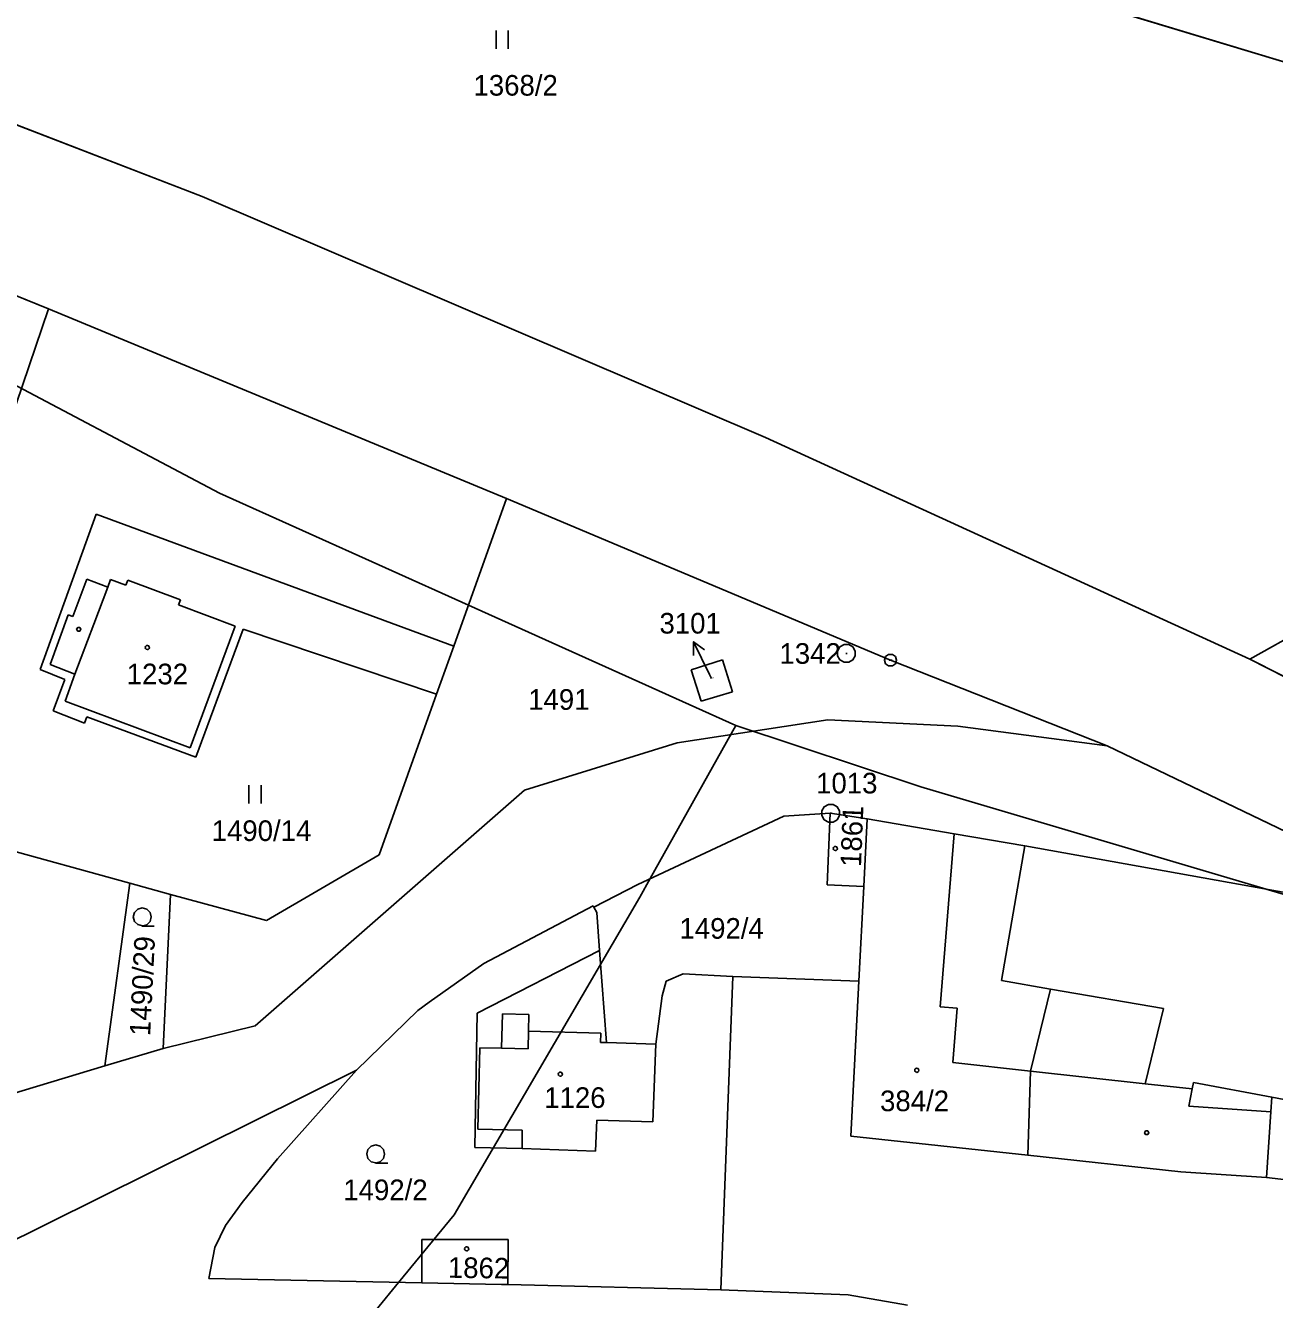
# Model space of a CAD drawing. Extents: x -779618 to -776429, y -1144546 to -1143350.
# Drawn here: x -777476.8 to -777373.9, y -1143853.5 to -1143748.5 of the extents above; entities that cross this region are included whole.
import ezdxf

# ---------------------------------------------------------------- set-up
doc = ezdxf.new("R2010")
doc.units = 0
for name, color, linetype in [('1', 7, 'Continuous'), ('11', 7, 'Continuous'), ('12', 7, 'Continuous'), ('2', 7, 'Continuous'), ('3', 7, 'Continuous'), ('4', 7, 'Continuous'), ('5', 7, 'Continuous'), ('7', 7, 'Continuous'), ('8', 7, 'Continuous')]:
    doc.layers.add(name, color=color, linetype=linetype)

msp = doc.modelspace()

# ---------------------------------------------------------------- linework, layer by layer
at = {"layer": '1'}
for p, q in [((-777547.63, -1143698.79), (-777364.95, -1143754.01)), ((-777556.08, -1143726.43), (-777462.27, -1143762.62)), ((-777415.86, -1143782.49), (-777462.27, -1143762.62)), ((-777494.83, -1143763.84), (-777474.95, -1143771.88)), ((-777487.19, -1143807.86), (-777474.95, -1143771.88)), ((-777437.2, -1143787.51), (-777474.95, -1143771.88)), ((-777375.94, -1143800.75), (-777415.86, -1143782.49)), ((-777375.94, -1143800.75), (-777349.24, -1143785.82)), ((-777441.55, -1143799.67), (-777437.2, -1143787.51)), ((-777405.54, -1143800.83), (-777437.2, -1143787.51)), ((-777471.01, -1143788.8), (-777475.63, -1143801.6)), ((-777441.55, -1143799.67), (-777471.01, -1143788.8)), ((-777462.81, -1143808.82), (-777458.9, -1143798.28)), ((-777458.9, -1143798.28), (-777442.96, -1143803.61)), ((-777442.96, -1143803.61), (-777441.55, -1143799.67)), ((-777421.98, -1143801.63), (-777419.39, -1143800.8)), ((-777419.39, -1143800.8), (-777418.56, -1143803.42)), ((-777387.68, -1143807.89), (-777405.54, -1143800.83)), ((-777334.23, -1143821.79), (-777375.94, -1143800.75)), ((-777475.63, -1143801.6), (-777473.61, -1143802.41)), ((-777421.16, -1143804.21), (-777421.98, -1143801.63)), ((-777473.61, -1143802.41), (-777474.56, -1143805)), ((-777447.69, -1143816.85), (-777442.96, -1143803.61)), ((-777418.56, -1143803.42), (-777421.16, -1143804.21)), ((-777474.56, -1143805), (-777471.98, -1143806.02)), ((-777471.98, -1143806.02), (-777471.78, -1143805.5)), ((-777471.78, -1143805.5), (-777462.81, -1143808.82)), ((-777423.12, -1143807.62), (-777410.71, -1143805.75)), ((-777410.71, -1143805.75), (-777400, -1143806.27)), ((-777400, -1143806.27), (-777387.68, -1143807.89)), ((-777435.72, -1143811.54), (-777423.12, -1143807.62)), ((-777356.13, -1143823.03), (-777387.68, -1143807.89)), ((-777457.92, -1143830.94), (-777435.72, -1143811.54)), ((-777489.08, -1143813.43), (-777468.25, -1143819.2)), ((-777410.51, -1143813.42), (-777414.33, -1143813.66)), ((-777410.76, -1143819.32), (-777410.51, -1143813.42)), ((-777407.46, -1143813.89), (-777410.51, -1143813.42)), ((-777414.33, -1143813.66), (-777426.36, -1143819.29)), ((-777407.75, -1143819.47), (-777407.46, -1143813.89)), ((-777400.29, -1143815.13), (-777407.46, -1143813.89)), ((-777394.47, -1143816.13), (-777400.29, -1143815.13)), ((-777394.47, -1143816.13), (-777396.39, -1143827.22)), ((-777369.47, -1143820.6), (-777394.47, -1143816.13)), ((-777456.98, -1143822.28), (-777447.69, -1143816.85)), ((-777468.25, -1143819.2), (-777470.29, -1143834.25)), ((-777468.25, -1143819.2), (-777464.88, -1143820.14)), ((-777430, -1143821.16), (-777426.36, -1143819.29)), ((-777407.75, -1143819.47), (-777410.76, -1143819.32)), ((-777408.15, -1143827.26), (-777407.75, -1143819.47)), ((-777464.88, -1143820.14), (-777465.49, -1143832.81)), ((-777464.88, -1143820.14), (-777456.98, -1143822.28)), ((-777430.05, -1143821.07), (-777439.06, -1143825.81)), ((-777430, -1143821.16), (-777430.05, -1143821.07)), ((-777430, -1143821.16), (-777429.76, -1143821.62)), ((-777429.52, -1143824.74), (-777429.76, -1143821.62)), ((-777429.52, -1143824.74), (-777439.62, -1143829.91)), ((-777429.52, -1143824.74), (-777428.95, -1143832.33)), ((-777439.06, -1143825.81), (-777443.57, -1143828.99)), ((-777422.63, -1143826.67), (-777424.04, -1143827.28)), ((-777418.55, -1143826.88), (-777422.63, -1143826.67)), ((-777419.52, -1143852.7), (-777418.55, -1143826.88)), ((-777408.15, -1143827.26), (-777418.55, -1143826.88)), ((-777396.39, -1143827.22), (-777392.36, -1143827.92)), ((-777424.04, -1143827.28), (-777424.38, -1143828.48)), ((-777408.15, -1143827.26), (-777408.81, -1143840.04)), ((-777392.36, -1143827.92), (-777394, -1143834.68)), ((-777443.57, -1143828.99), (-777444.5, -1143829.67)), ((-777424.9, -1143832.45), (-777424.38, -1143828.48)), ((-777444.5, -1143829.67), (-777449.55, -1143834.59)), ((-777439.81, -1143840.98), (-777439.62, -1143829.91)), ((-777465.49, -1143832.81), (-777457.92, -1143830.94)), ((-777428.95, -1143832.33), (-777424.9, -1143832.45)), ((-777424.9, -1143832.45), (-777425.13, -1143838.85)), ((-777465.49, -1143832.81), (-777470.29, -1143834.25)), ((-777470.29, -1143834.25), (-777506.15, -1143845.05)), ((-777449.55, -1143834.59), (-777486.78, -1143853.07)), ((-777449.55, -1143834.59), (-777456.06, -1143841.9)), ((-777394, -1143834.68), (-777394.22, -1143841.61)), ((-777374.13, -1143836.83), (-777374.21, -1143838.03)), ((-777347.87, -1143841.8), (-777374.13, -1143836.83)), ((-777429.76, -1143838.71), (-777429.86, -1143841.27)), ((-777425.13, -1143838.85), (-777429.76, -1143838.71)), ((-777374.21, -1143838.03), (-777374.57, -1143843.43)), ((-777394.22, -1143841.61), (-777408.81, -1143840.04)), ((-777456.06, -1143841.9), (-777458.98, -1143845.51)), ((-777435.91, -1143841.04), (-777439.81, -1143840.98)), ((-777429.86, -1143841.27), (-777435.91, -1143841.04)), ((-777381.61, -1143842.97), (-777394.22, -1143841.61)), ((-777374.57, -1143843.43), (-777381.61, -1143842.97)), ((-777374.57, -1143843.43), (-777344.36, -1143847.04)), ((-777458.98, -1143845.51), (-777460.37, -1143847.4)), ((-777460.37, -1143847.4), (-777461.25, -1143849.21)), ((-777461.25, -1143849.21), (-777461.74, -1143851.77)), ((-777444.18, -1143852.13), (-777444.17, -1143848.54)), ((-777444.17, -1143848.54), (-777437.07, -1143848.56)), ((-777437.07, -1143848.56), (-777437.09, -1143852.27)), ((-777461.74, -1143851.77), (-777444.18, -1143852.13)), ((-777444.18, -1143852.13), (-777437.61, -1143852.26)), ((-777437.61, -1143852.26), (-777437.09, -1143852.27)), ((-777437.09, -1143852.27), (-777419.52, -1143852.7)), ((-777409.04, -1143853.1), (-777419.52, -1143852.7)), ((-777404.16, -1143853.96), (-777409.04, -1143853.1))]:
    msp.add_line(p, q, dxfattribs=at)
at = {"layer": '11'}
for points in [[(-777547.63, -1143698.79), (-777364.95, -1143754.01), (-777362.08, -1143759.74), (-777358.14, -1143760.61), (-777354.56, -1143760.13), (-777348.72, -1143768.82), (-777340.59, -1143770.61), (-777339.43, -1143766.44), (-777335.02, -1143764.48), (-777321.99, -1143767.59), (-777306.65, -1143771.6), (-777305.36, -1143768.26), (-777286.39, -1143773.98), (-777252.03, -1143784.34), (-777238.03, -1143787.25), (-777223.03, -1143791.52), (-777208.67, -1143795.71)], [(-777215.44, -1143846.33), (-777291.06, -1143838.91), (-777294.79, -1143837.91), (-777307.07, -1143834.06), (-777326.59, -1143824.61), (-777334.23, -1143821.79), (-777375.94, -1143800.75), (-777415.86, -1143782.49), (-777462.27, -1143762.62), (-777554.92, -1143726.88)], [(-777521.49, -1143753.86), (-777516.57, -1143757.49), (-777516.32, -1143757.62), (-777506.06, -1143763.09), (-777499.08, -1143767.2), (-777481.34, -1143776.24), (-777460.86, -1143787.05), (-777440.34, -1143796.28), (-777418.3, -1143806.19)], [(-777521.49, -1143753.86), (-777515.73, -1143755.37), (-777494.83, -1143763.84), (-777474.95, -1143771.88), (-777437.2, -1143787.51), (-777405.54, -1143800.83), (-777387.68, -1143807.89), (-777356.13, -1143823.03), (-777352.24, -1143824.36), (-777344.73, -1143827.04), (-777336.84, -1143829.8), (-777324.83, -1143836.1), (-777303.85, -1143844.86), (-777292.27, -1143847.75), (-777289.53, -1143848.43), (-777281.88, -1143848.9), (-777167.58, -1143858.82), (-777035.36, -1143870.54), (-777014.02, -1143874.66), (-776998.39, -1143882.22), (-776992.99, -1143881.07), (-776972.79, -1143876.78), (-776970.83, -1143876.37), (-776959.34, -1143880.62)], [(-777497.86, -1143963.05), (-777497.46, -1143948.45), (-777496.32, -1143934.15), (-777492.21, -1143927.38), (-777485.12, -1143915.71), (-777483.6, -1143913.21), (-777468.38, -1143879.27), (-777447.94, -1143854.35), (-777446.1, -1143852.09), (-777441.52, -1143846.51), (-777426.21, -1143820.36), (-777425.35, -1143818.82), (-777418.3, -1143806.19)], [(-777418.3, -1143806.19), (-777403.06, -1143811.25), (-777374.59, -1143819.68), (-777369.17, -1143821.29), (-777341.76, -1143831.4), (-777336.43, -1143834.11), (-777325.63, -1143839.6), (-777311.72, -1143846.67), (-777306.4, -1143849.25), (-777294.09, -1143855.23), (-777285.59, -1143859.36), (-777258.07, -1143878.57), (-777228.36, -1143900.38)]]:
    msp.add_lwpolyline(points, dxfattribs=at)
at = {"layer": '12'}
for p, q in [((-777469.84, -1143794.17), (-777470.07, -1143794.8)), ((-777468.56, -1143794.65), (-777469.84, -1143794.17)), ((-777468.4, -1143794.23), (-777468.56, -1143794.65)), ((-777464.08, -1143795.85), (-777468.4, -1143794.23)), ((-777471.21, -1143797.86), (-777470.07, -1143794.8)), ((-777464.24, -1143796.27), (-777464.08, -1143795.85)), ((-777459.56, -1143798.03), (-777464.24, -1143796.27)), ((-777472.78, -1143801.97), (-777471.21, -1143797.86)), ((-777459.56, -1143798.03), (-777463.27, -1143808.03)), ((-777473.56, -1143804.21), (-777472.78, -1143801.97)), ((-777463.27, -1143808.03), (-777473.56, -1143804.21)), ((-777410.76, -1143819.32), (-777410.51, -1143813.42)), ((-777407.46, -1143813.89), (-777410.51, -1143813.42)), ((-777407.75, -1143819.47), (-777407.46, -1143813.89)), ((-777407.75, -1143819.47), (-777407.46, -1143813.89)), ((-777400.29, -1143815.13), (-777407.46, -1143813.89)), ((-777401.46, -1143829.38), (-777400.29, -1143815.13)), ((-777394.47, -1143816.13), (-777396.39, -1143827.22)), ((-777369.47, -1143820.6), (-777394.47, -1143816.13)), ((-777407.75, -1143819.47), (-777410.76, -1143819.32)), ((-777408.15, -1143827.26), (-777407.75, -1143819.47)), ((-777396.39, -1143827.22), (-777392.36, -1143827.92)), ((-777408.15, -1143827.26), (-777408.81, -1143840.04)), ((-777392.36, -1143827.92), (-777383.05, -1143829.53)), ((-777400.06, -1143829.5), (-777401.46, -1143829.38)), ((-777400.42, -1143833.97), (-777400.06, -1143829.5)), ((-777383.05, -1143829.53), (-777384.55, -1143835.72)), ((-777435.42, -1143832.85), (-777435.38, -1143831.38)), ((-777429.42, -1143831.56), (-777435.38, -1143831.38)), ((-777429.45, -1143832.31), (-777429.42, -1143831.56)), ((-777428.95, -1143832.33), (-777429.45, -1143832.31)), ((-777428.95, -1143832.33), (-777424.9, -1143832.45)), ((-777424.9, -1143832.45), (-777425.13, -1143838.85)), ((-777439.39, -1143832.75), (-777439.56, -1143839.47)), ((-777437.6, -1143832.8), (-777439.39, -1143832.75)), ((-777437.6, -1143832.8), (-777435.42, -1143832.85)), ((-777394, -1143834.68), (-777400.42, -1143833.97)), ((-777394, -1143834.68), (-777394.22, -1143841.61)), ((-777380.58, -1143835.61), (-777380.68, -1143836.15)), ((-777374.13, -1143836.83), (-777380.58, -1143835.61)), ((-777384.55, -1143835.72), (-777380.68, -1143836.15)), ((-777347.87, -1143841.8), (-777374.13, -1143836.83)), ((-777429.76, -1143838.71), (-777429.86, -1143841.27)), ((-777425.13, -1143838.85), (-777429.76, -1143838.71)), ((-777439.56, -1143839.47), (-777435.91, -1143839.53)), ((-777435.91, -1143839.53), (-777435.91, -1143841.04)), ((-777394.22, -1143841.61), (-777408.81, -1143840.04)), ((-777429.86, -1143841.27), (-777435.91, -1143841.04)), ((-777444.18, -1143852.13), (-777444.17, -1143848.54)), ((-777444.17, -1143848.54), (-777437.07, -1143848.56)), ((-777437.07, -1143848.56), (-777437.09, -1143852.27)), ((-777444.18, -1143852.13), (-777437.61, -1143852.26)), ((-777437.61, -1143852.26), (-777437.09, -1143852.27))]:
    msp.add_line(p, q, dxfattribs=at)
at = {"layer": '3'}
for p, q in [((-777438.05, -1143748.95), (-777438.05, -1143750.45)), ((-777437.05, -1143750.45), (-777437.05, -1143748.95)), ((-777458.43, -1143811.12), (-777458.43, -1143812.62)), ((-777457.43, -1143812.62), (-777457.43, -1143811.12))]:
    msp.add_line(p, q, dxfattribs=at)
for points in [[(-777467.21, -1143822.71), (-777467.59, -1143822.61), (-777467.86, -1143822.34), (-777467.96, -1143821.97), (-777467.86, -1143821.6), (-777467.59, -1143821.33), (-777467.22, -1143821.23), (-777466.85, -1143821.33), (-777466.58, -1143821.6), (-777466.48, -1143821.98), (-777466.58, -1143822.36), (-777466.85, -1143822.63), (-777467.23, -1143822.73), (-777466.23, -1143822.73)], [(-777447.97, -1143842.24), (-777448.35, -1143842.14), (-777448.62, -1143841.87), (-777448.72, -1143841.5), (-777448.62, -1143841.13), (-777448.35, -1143840.86), (-777447.98, -1143840.76), (-777447.61, -1143840.86), (-777447.34, -1143841.13), (-777447.24, -1143841.51), (-777447.34, -1143841.89), (-777447.61, -1143842.16), (-777447.99, -1143842.26), (-777446.99, -1143842.26)]]:
    msp.add_lwpolyline(points, dxfattribs=at)
at = {"layer": '4'}
for p, q in [((-777472.93, -1143797.23), (-777471.79, -1143794.16)), ((-777471.79, -1143794.16), (-777470.07, -1143794.8)), ((-777469.84, -1143794.17), (-777470.07, -1143794.8)), ((-777468.56, -1143794.65), (-777469.84, -1143794.17)), ((-777468.4, -1143794.23), (-777468.56, -1143794.65)), ((-777464.08, -1143795.85), (-777468.4, -1143794.23)), ((-777471.21, -1143797.86), (-777470.07, -1143794.8)), ((-777464.24, -1143796.27), (-777464.08, -1143795.85)), ((-777459.56, -1143798.03), (-777464.24, -1143796.27)), ((-777474.81, -1143801.17), (-777473.33, -1143797.08)), ((-777473.33, -1143797.08), (-777472.93, -1143797.23)), ((-777472.78, -1143801.97), (-777471.21, -1143797.86)), ((-777459.56, -1143798.03), (-777463.27, -1143808.03)), ((-777472.78, -1143801.97), (-777474.81, -1143801.17)), ((-777473.56, -1143804.21), (-777472.78, -1143801.97)), ((-777463.27, -1143808.03), (-777473.56, -1143804.21)), ((-777401.46, -1143829.38), (-777400.29, -1143815.13)), ((-777392.36, -1143827.92), (-777383.05, -1143829.53)), ((-777437.6, -1143832.8), (-777437.52, -1143829.97)), ((-777435.35, -1143830.02), (-777437.52, -1143829.97)), ((-777435.38, -1143831.38), (-777435.35, -1143830.02)), ((-777400.06, -1143829.5), (-777401.46, -1143829.38)), ((-777400.42, -1143833.97), (-777400.06, -1143829.5)), ((-777383.05, -1143829.53), (-777384.55, -1143835.72)), ((-777435.42, -1143832.85), (-777435.38, -1143831.38)), ((-777429.42, -1143831.56), (-777435.38, -1143831.38)), ((-777429.45, -1143832.31), (-777429.42, -1143831.56)), ((-777428.95, -1143832.33), (-777429.45, -1143832.31)), ((-777439.39, -1143832.75), (-777439.56, -1143839.47)), ((-777437.6, -1143832.8), (-777439.39, -1143832.75)), ((-777437.6, -1143832.8), (-777435.42, -1143832.85)), ((-777394, -1143834.68), (-777400.42, -1143833.97)), ((-777384.55, -1143835.72), (-777394, -1143834.68)), ((-777380.58, -1143835.61), (-777380.68, -1143836.15)), ((-777374.13, -1143836.83), (-777380.58, -1143835.61)), ((-777384.55, -1143835.72), (-777380.68, -1143836.15)), ((-777380.68, -1143836.15), (-777380.95, -1143837.57)), ((-777380.95, -1143837.57), (-777374.21, -1143838.03)), ((-777439.56, -1143839.47), (-777435.91, -1143839.53)), ((-777435.91, -1143839.53), (-777435.91, -1143841.04))]:
    msp.add_line(p, q, dxfattribs=at)
at = {"layer": '5'}
for points in [[(-777472.36, -1143798.13), (-777472.27, -1143798.28), (-777472.36, -1143798.43), (-777472.54, -1143798.43), (-777472.63, -1143798.28), (-777472.54, -1143798.13)], [(-777466.8, -1143799.61), (-777466.7, -1143799.63), (-777466.65, -1143799.72), (-777466.63, -1143799.78), (-777466.65, -1143799.87), (-777466.73, -1143799.94), (-777466.8, -1143799.95), (-777466.89, -1143799.92), (-777466.95, -1143799.86), (-777466.97, -1143799.78), (-777466.95, -1143799.69), (-777466.87, -1143799.62)], [(-777410.09, -1143816.17), (-777409.99, -1143816.19), (-777409.94, -1143816.28), (-777409.92, -1143816.34), (-777409.94, -1143816.43), (-777410.02, -1143816.5), (-777410.09, -1143816.51), (-777410.18, -1143816.48), (-777410.24, -1143816.42), (-777410.26, -1143816.34), (-777410.24, -1143816.25), (-777410.16, -1143816.18)], [(-777403.38, -1143834.44), (-777403.28, -1143834.46), (-777403.23, -1143834.55), (-777403.21, -1143834.61), (-777403.23, -1143834.7), (-777403.31, -1143834.77), (-777403.38, -1143834.78), (-777403.47, -1143834.75), (-777403.53, -1143834.69), (-777403.55, -1143834.61), (-777403.53, -1143834.52), (-777403.45, -1143834.45)], [(-777432.76, -1143834.76), (-777432.66, -1143834.78), (-777432.61, -1143834.87), (-777432.59, -1143834.93), (-777432.61, -1143835.02), (-777432.69, -1143835.09), (-777432.76, -1143835.1), (-777432.85, -1143835.07), (-777432.91, -1143835.01), (-777432.93, -1143834.93), (-777432.91, -1143834.84), (-777432.83, -1143834.77)], [(-777384.34, -1143839.6), (-777384.25, -1143839.75), (-777384.34, -1143839.9), (-777384.52, -1143839.9), (-777384.61, -1143839.75), (-777384.52, -1143839.6)], [(-777440.48, -1143849.15), (-777440.38, -1143849.17), (-777440.33, -1143849.26), (-777440.31, -1143849.32), (-777440.33, -1143849.41), (-777440.41, -1143849.48), (-777440.48, -1143849.49), (-777440.57, -1143849.46), (-777440.63, -1143849.4), (-777440.65, -1143849.32), (-777440.63, -1143849.23), (-777440.55, -1143849.16)]]:
    msp.add_lwpolyline(points, close=True, dxfattribs=at)
at = {"layer": '7'}
for p in [(-777421.78, -1143799.31), (-777420.31, -1143802.32)]:
    msp.add_line(p, (-777420.46, -1143802), dxfattribs=at)
msp.add_lwpolyline([(-777421.79, -1143800.43), (-777421.78, -1143799.31), (-777420.89, -1143799.98)], dxfattribs=at)
at = {"layer": '8'}
for p, q in [((-777409.23, -1143800.26), (-777409.13, -1143800.26)), ((-777405.66, -1143800.83), (-777405.42, -1143800.83)), ((-777410.52, -1143813.43), (-777410.42, -1143813.43))]:
    msp.add_line(p, q, dxfattribs=at)
for points in [[(-777408.99, -1143799.54), (-777408.65, -1143799.73), (-777408.46, -1143800.07), (-777408.46, -1143800.46), (-777408.65, -1143800.8), (-777408.99, -1143800.99), (-777409.38, -1143800.99), (-777409.72, -1143800.8), (-777409.91, -1143800.46), (-777409.91, -1143800.07), (-777409.72, -1143799.73), (-777409.38, -1143799.54)], [(-777405.39, -1143800.35), (-777405.14, -1143800.53), (-777405.04, -1143800.82), (-777405.14, -1143801.11), (-777405.39, -1143801.29), (-777405.7, -1143801.29), (-777405.95, -1143801.11), (-777406.05, -1143800.82), (-777405.95, -1143800.53), (-777405.7, -1143800.35)], [(-777410.28, -1143812.71), (-777409.94, -1143812.9), (-777409.75, -1143813.24), (-777409.75, -1143813.63), (-777409.94, -1143813.97), (-777410.28, -1143814.16), (-777410.67, -1143814.16), (-777411.01, -1143813.97), (-777411.2, -1143813.63), (-777411.2, -1143813.24), (-777411.01, -1143812.9), (-777410.67, -1143812.71)]]:
    msp.add_lwpolyline(points, close=True, dxfattribs=at)

# ---------------------------------------------------------------- texts
at = {"layer": '2'}
for s, height, p in [('1368/2', 1.7, (-777439.92, -1143754.31)), ('1232', 1.7, (-777468.5, -1143802.81)), ('3101', 0.1, (-777420.43, -1143802.32)), ('1491', 1.7, (-777435.41, -1143804.91)), ('1490/14', 1.7, (-777461.5, -1143815.72)), ('1492/4', 1.7, (-777422.94, -1143823.77)), ('1126', 1.7, (-777434.09, -1143837.71)), ('384/2', 1.7, (-777406.41, -1143837.98)), ('1492/2', 1.7, (-777450.65, -1143845.31))]:
    msp.add_text(s, height=height, dxfattribs=at).set_placement(p)
for s, rotation, p in [('1861', 87.6625, (-777407.98, -1143817.88)), ('1490/29', 87.1469, (-777466.57, -1143831.81)), ('1862', 359.1872, (-777442.04, -1143851.7))]:
    msp.add_text(s, height=1.7, rotation=rotation, dxfattribs=at).set_placement(p)
at = {"layer": '7'}
msp.add_text('3101', height=1.7, dxfattribs=at).set_placement((-777424.59, -1143798.63))
at = {"layer": '8'}
for s, p in [('1342', (-777414.7, -1143801.12)), ('1013', (-777411.68, -1143811.8))]:
    msp.add_text(s, height=1.7, dxfattribs=at).set_placement(p)

doc.saveas('drawing.dxf')
